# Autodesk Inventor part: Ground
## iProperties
Created: 2006-07
Part Number: Ground
Document SubType Name: Modeling
Designer: Maxime Debono
Mass: 30.6792 g
Surface Area: 140.758 cm^2
Volume: 30.6792 cm^3
Density: 1 g/cm^3
Author: Maxime Debono
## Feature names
1. Extrusion1
2. Mirror1
3. Extrusion2
